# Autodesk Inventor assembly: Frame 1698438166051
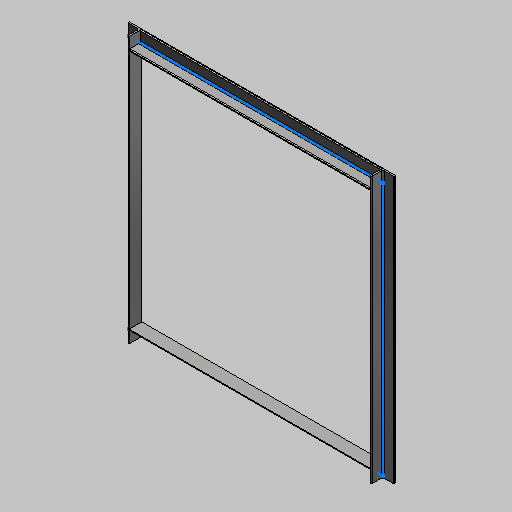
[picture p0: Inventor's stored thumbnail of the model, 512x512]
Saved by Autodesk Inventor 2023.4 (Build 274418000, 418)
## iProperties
Created: 2023-10
Part Number: Frame 1698438166051
Material: Steel, Mild
Document SubType Name: Assembly
Designer: Fred L.
Mass: 2431.55 g
Surface Area: 2020.83 cm^2
Volume: 309.752 cm^3
Density: 7.85 g/cm^3
_FrameDoc: Frame Assembly
_Version: 25.0.0
Quantity: 0
Mass: 5.36
Author: Fred L.
Revision Number: 00
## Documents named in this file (6)
- C:\Vault Workspace\Designs\_Fred\IV Forum\FG2\FG\Frame\Frame 1698438166051.iam
- C:\Vault Workspace\Designs\_Fred\IV Forum\FG2\FG\Frame\Skeleton 1698438166052.ipt
- C:\Vault Workspace\Designs\_Fred\IV Forum\FG2\FG\Frame\AISC (L 1 x 1 x 1_8) 1698438168295.ipt
- C:\Vault Workspace\Designs\_Fred\IV Forum\FG2\FG\Frame\AISC (L 1 x 1 x 1_8) 1698438168341.ipt
- C:\Vault Workspace\Designs\_Fred\IV Forum\FG2\FG\Frame\AISC (L 1 x 1 x 1_8) 1698438168386.ipt
- C:\Vault Workspace\Designs\_Fred\IV Forum\FG2\FG\Frame\AISC (L 1 x 1 x 1_8) 1698438168431.ipt
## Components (5 placed, 3 different names)
1. Reference Skeleton
2. AISC (L 1 x 1 x 1/8) - 21:1
3. AISC (L 1 x 1 x 1/8) - 19:2
4. AISC (L 1 x 1 x 1/8) - 21:3
5. AISC (L 1 x 1 x 1/8) - 19:4
